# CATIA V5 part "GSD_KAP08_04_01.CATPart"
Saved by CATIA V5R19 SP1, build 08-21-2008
Part number: GSD_ANALYSIS_03
Description: Beispieldatensatz: Flächenkrümmungsanalyse  Maik Hertha IT Consultants
Bounding box of the stored display mesh (mm): x -107.737 to -15.264, y -127.079 to 435.495, z -8.778 to 167.189
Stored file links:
  \GSD_BUCH_UEBUNG\GSD_KAP08_04_01.CATPart
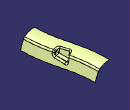
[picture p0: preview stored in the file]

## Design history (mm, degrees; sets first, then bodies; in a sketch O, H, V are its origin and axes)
AxisSystem1 "Absolute Axis System": origin (0, 0, 0), X (1, 0, 0), Y (0, 1, 0), Z (0, 0, 1)
Set1
  DatumSurface1 "X-Fillet.6"
Body1 (main body)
